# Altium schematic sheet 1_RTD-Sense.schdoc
size 307 x 218 mm; Symbol: Drawing-Symbol_A4; Device: Drawing-Symbol_A4; @Project Name: Temp_Con_V116; @Page Count: 2; @Update Date: 2025-01-28; @Create Date: 2025-01-22; @Schematic Name: SENS_485; @Page No: 1; @Page Name: RTD-Sense; Company: EasyEDA.com; Version: V1.0; Page Size: A4; @Create Time: 19:48:27; @Update Time: 02:04:33; Width: 1170; Height: 825; Region Start: 1; X Region Count: 6; Y Region Count: 4; Blade Width: 10; Title Block Position: 3; @Board Name: TEMP_SENS_485
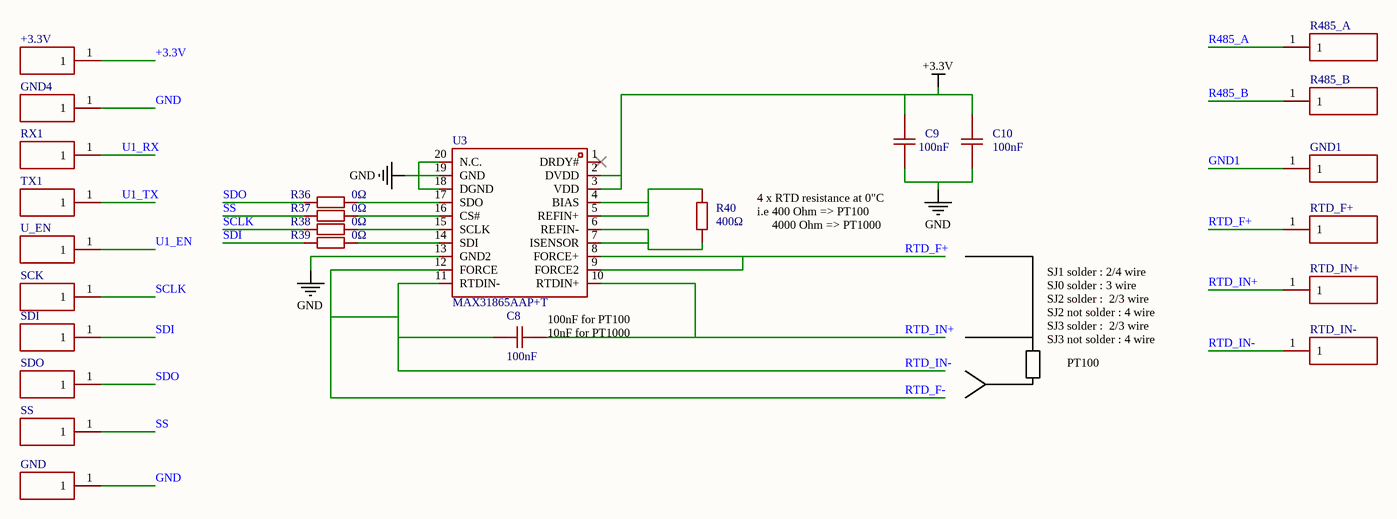
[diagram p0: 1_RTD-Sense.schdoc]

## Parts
+3.3V  (no value)  [S_FT]
C8  100nF  [C0805]
C9  100nF  [C0805]
C10  100nF  [C0805]
GND  (no value)  [S_FT]
GND1  (no value)  [B_FT]
GND4  (no value)  [S_FT]
R36  0Ω  [R0805]
R37  0Ω  [R0805]
R38  0Ω  [R0805]
R39  0Ω  [R0805]
R40  400Ω  [R0805]
R485_A  (no value)  [B_FT]
R485_B  (no value)  [B_FT]
RTD_F+  (no value)  [B_FT]
RTD_IN+  (no value)  [B_FT]
RTD_IN-  (no value)  [B_FT]
RX1  (no value)  [S_FT]
SCK  (no value)  [S_FT]
SDI  (no value)  [S_FT]
SDO  (no value)  [S_FT]
SS  (no value)  [S_FT]
TX1  (no value)  [S_FT]
U3  MAX31865AAP+T  [SSOP-20_L7.2-W5.3-P0.65-LS7.8-BL]
U_EN  (no value)  [S_FT]

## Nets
+3.3V: +3.3V.1 C9.1 C10.1 U3.2(DVDD) U3.3(VDD)
GND: C9.2 C10.2 GND.1 GND4.1 U3.13(GND2) U3.18(DGND) U3.19(GND) U3.20(N.C.)
GND1: GND1.1
R485_A: R485_A.1
R485_B: R485_B.1
RTD_F+: RTD_F+.1 U3.8(FORCE+) U3.9(FORCE2)
RTD_F-: C8.2 RTD_IN-.1 U3.11(RTDIN-) U3.12(FORCE)  [also labelled RTD_IN-]
RTD_IN+: C8.1 RTD_IN+.1 U3.10(RTDIN+)
SCLK: R38.1 SCK.1
SDI: R39.1 SDI.1
SDO: R36.1 SDO.1
SS: R37.1 SS.1
U1_EN: U_EN.1
U1_RX: RX1.1
U1_TX: TX1.1
NetR36_2: R36.2 U3.17(SDO)
NetR37_2: R37.2 U3.16(CS#)
NetR38_2: R38.2 U3.15(SCLK)
NetR39_2: R39.2 U3.14(SDI)
NetR40_1: R40.1 U3.6(REFIN-) U3.7(ISENSOR)
NetR40_2: R40.2 U3.4(BIAS) U3.5(REFIN+)

Not connected (* = marked no-connect by the designer): U3 1(DRDY#)*

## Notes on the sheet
- 4 x RTD resistance at 0"C
  i.e 400 Ohm => PT100
  4000 Ohm => PT1000
- SJ1 solder : 2/4 wire
  SJ0 solder : 3 wire
  SJ2 solder :  2/3 wire
  SJ2 not solder : 4 wire
  SJ3 solder :  2/3 wire
  SJ3 not solder : 4 wire
- (near C8) 100nF for PT100
  10nF for PT1000
- PT100

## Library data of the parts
+3.3V GND GND4 RX1 SCK SDI SDO SS TX1 U_EN = S_TM: Add into BOM: no; Convert to PCB: yes
C8-C10 = CC0805KRX7R9BB104: Manufacturer: YAGEO(国巨); Add into BOM: yes; Tolerance: ±10%; Check: true
GND1 R485_A R485_B RTD_F+ RTD_IN+ RTD_IN- = B_TM: Add into BOM: no; Convert to PCB: yes
R36-R39 = RC0805JR-070RL: Manufacturer: YAGEO(国巨); Add into BOM: yes; Tolerance: ±5%; Check: true
R40 = TR0805B400RP0525Z: Manufacturer: EVER OHMS(天二科技); Add into BOM: yes; Tolerance: ±0.1%; Temperature Coefficient: ±25ppm/℃; Check: true
U3 = MAX31865AAP+T: Manufacturer: ADI(亚德诺)/MAXIM(美信); Add into BOM: yes; Interface: SPI; number of channels: 1; Supply Voltage: 3V~3.6V; Integral nonlinearity: 1LSB; resolution: 15Bit; Check: true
